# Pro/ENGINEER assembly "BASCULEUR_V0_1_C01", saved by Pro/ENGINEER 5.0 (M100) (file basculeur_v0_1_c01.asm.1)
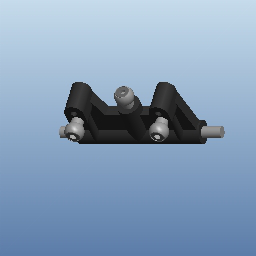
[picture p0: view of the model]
Units: millimeter Newton Second (mmNs); MM, TONNE, HOURS

Other components: 80659600-BASCULEUR_AV_C01, E-ROTULE_VIS_C02, E-ROTULE_VIS_C02, E-ROTULE_VIS_C02

Other named items: A-DROITE, A-DESSUS, A-FACE, A-R0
